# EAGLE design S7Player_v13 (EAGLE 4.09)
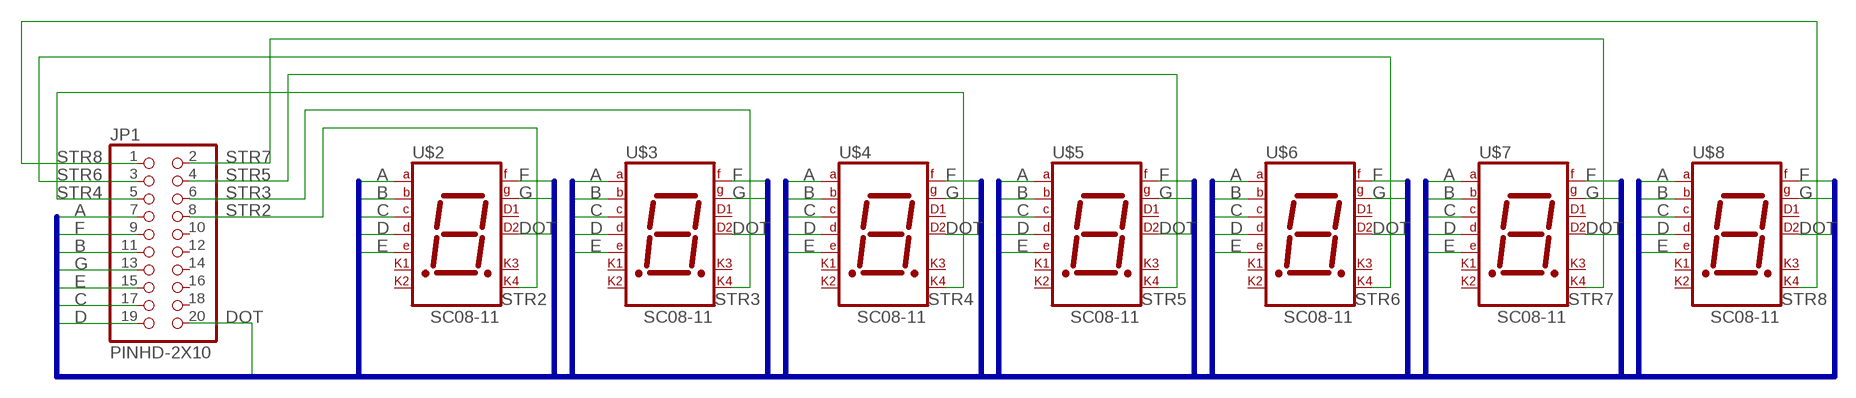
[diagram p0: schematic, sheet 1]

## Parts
JP1  PINHD-2X10  [2X10]
U$2  SC08-11  [SC08-11]
U$3  SC08-11  [SC08-11]
U$4  SC08-11  [SC08-11]
U$5  SC08-11  [SC08-11]
U$6  SC08-11  [SC08-11]
U$7  SC08-11  [SC08-11]
U$8  SC08-11  [SC08-11]

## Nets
A: JP1.7 U$2.1(A) U$3.1(A) U$4.1(A) U$5.1(A) U$6.1(A) U$7.1(A) U$8.1(A)
B: JP1.11 U$2.14(B) U$3.14(B) U$4.14(B) U$5.14(B) U$6.14(B) U$7.14(B) U$8.14(B)
C: JP1.17 U$2.12(C) U$3.12(C) U$4.12(C) U$5.12(C) U$6.12(C) U$7.12(C) U$8.12(C)
D: JP1.19 U$2.10(D) U$3.10(D) U$4.10(D) U$5.10(D) U$6.10(D) U$7.10(D) U$8.10(D)
DOT: JP1.20 U$2.9(D2) U$3.9(D2) U$4.9(D2) U$5.9(D2) U$6.9(D2) U$7.9(D2) U$8.9(D2)
E: JP1.15 U$2.4(E) U$3.4(E) U$4.4(E) U$5.4(E) U$6.4(E) U$7.4(E) U$8.4(E)
F: JP1.9 U$2.2(F) U$3.2(F) U$4.2(F) U$5.2(F) U$6.2(F) U$7.2(F) U$8.2(F)
G: JP1.13 U$2.13(G) U$3.13(G) U$4.13(G) U$5.13(G) U$6.13(G) U$7.13(G) U$8.13(G)
STR2: JP1.8 U$2.16(M4)
STR3: JP1.6 U$3.16(M4)
STR4: JP1.5 U$4.16(M4)
STR5: JP1.4 U$5.16(M4)
STR6: JP1.3 U$6.16(M4)
STR7: JP1.2 U$7.16(M4)
STR8: JP1.1 U$8.16(M4)
Unconnected: JP1.10 JP1.12 JP1.14 JP1.16 JP1.18 U$2.3(M1) U$2.5(M2) U$2.6(D1) U$2.11(M3) U$3.3(M1) U$3.5(M2) U$3.6(D1) U$3.11(M3) U$4.3(M1) U$4.5(M2) U$4.6(D1) U$4.11(M3) U$5.3(M1) U$5.5(M2) U$5.6(D1) U$5.11(M3) U$6.3(M1) U$6.5(M2) U$6.6(D1) U$6.11(M3) U$7.3(M1) U$7.5(M2) U$7.6(D1) U$7.11(M3) U$8.3(M1) U$8.5(M2) U$8.6(D1) U$8.11(M3)

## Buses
BUS:A,B,C,D,E,F,G,DOT

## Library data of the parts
JP1 = PINHEAD:PINHD-2X10
U$2-U$8 = SPECIAL:SC08-11

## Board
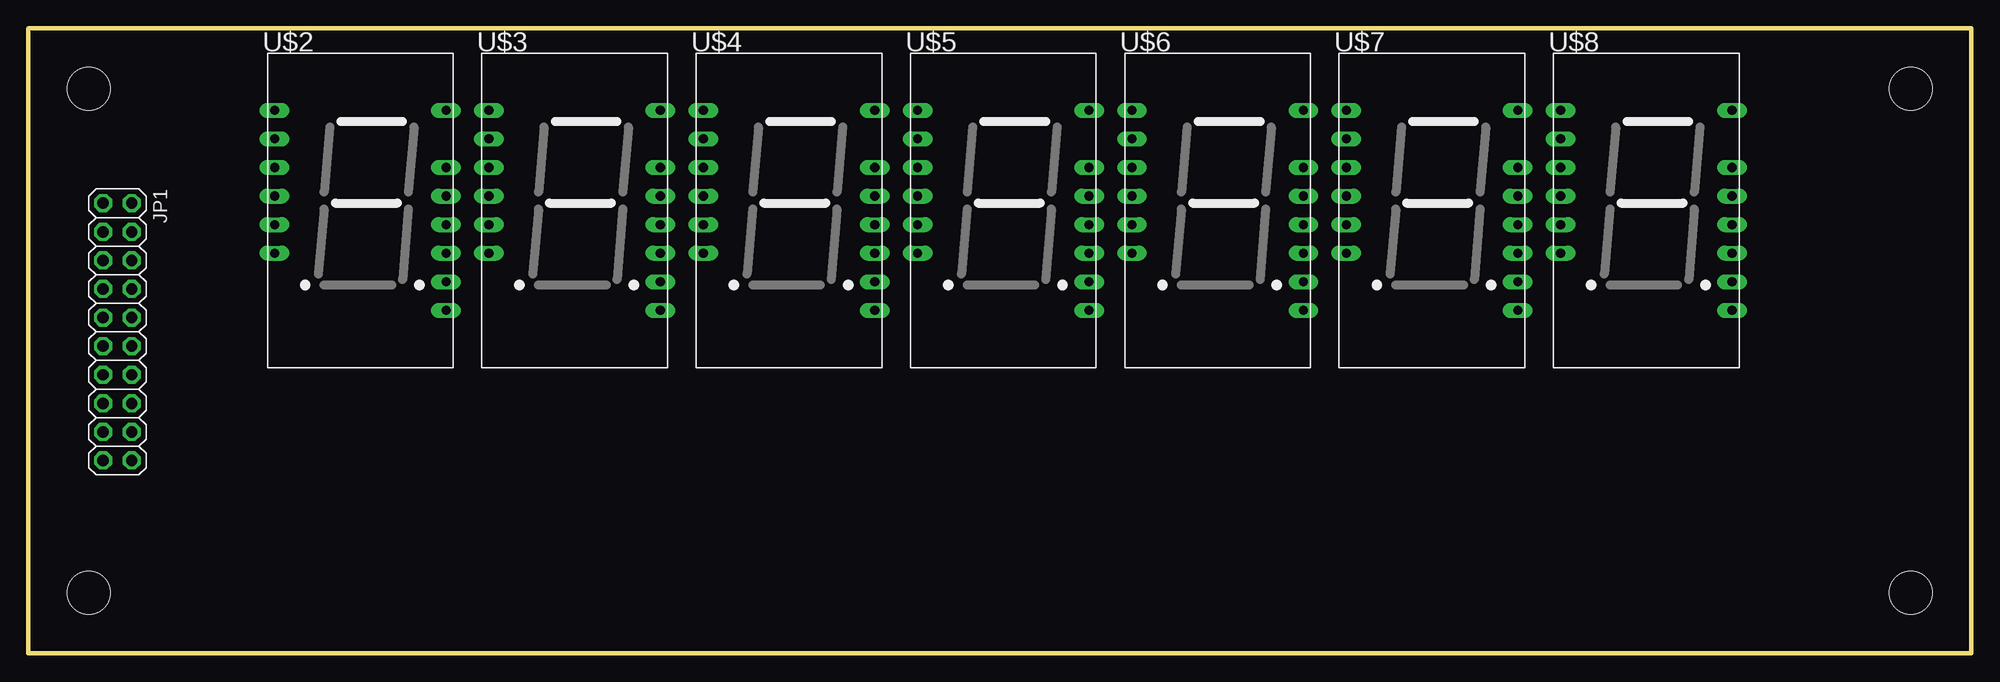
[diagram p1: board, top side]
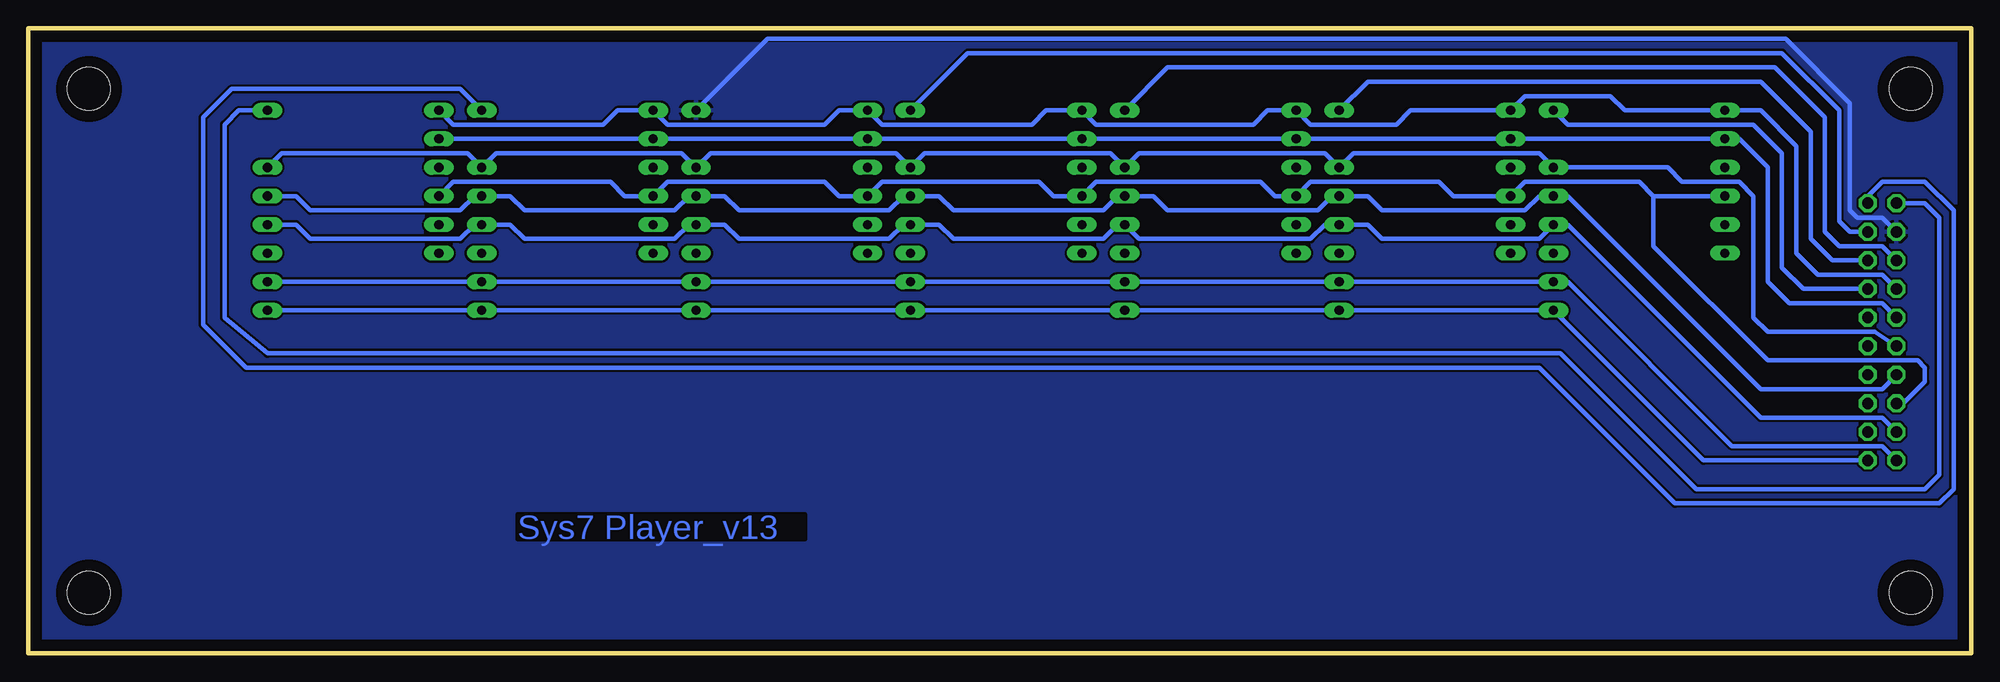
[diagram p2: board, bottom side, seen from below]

Size 172.72 x 55.56 mm. Coordinates in mm from the lower left corner, seen from the top.
Outline: 0,0 172.72,0 172.72,55.56 0,55.56 0,0
Copper layers used: Bottom
Holes 3.81 mm at 5.4,50.16 167.32,50.16 5.4,5.4 167.32,5.4
bKeepout: area 112.1,8.9 to 129.9,14

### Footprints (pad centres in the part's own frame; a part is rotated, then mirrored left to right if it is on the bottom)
2X10 = drill 1.016 pad 1.6 octagon: 1 -11.43,-1.27; 2 -11.43,1.27; 3 -8.89,-1.27; 4 -8.89,1.27; 5 -6.35,-1.27; 6 -6.35,1.27; 7 -3.81,-1.27; 8 -3.81,1.27; 9 -1.27,-1.27; 10 -1.27,1.27; 11 1.27,-1.27; 12 1.27,1.27; 13 3.81,-1.27; 14 3.81,1.27; 15 6.35,-1.27; 16 6.35,1.27; 17 8.89,-1.27; 18 8.89,1.27; 19 11.43,-1.27; 20 11.43,1.27
SC08-11 = drill 0.813 pad 1.27 long: 1 0,17.78; 2 0,15.24; 3 0,12.7; 4 0,10.16; 5 0,7.62; 6 0,5.08; 9 15.24,0; 10 15.24,2.54; 11 15.24,5.08; 12 15.24,7.62; 13 15.24,10.16; 14 15.24,12.7; 16 15.24,17.78

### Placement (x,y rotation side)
JP1  7.94,28.57 270 top
U$2  21.91,30.48 0 top
U$3  40.96,30.48 0 top
U$4  60.01,30.48 0 top
U$5  79.06,30.48 0 top
U$6  98.11,30.48 0 top
U$7  117.16,30.48 0 top
U$8  136.21,30.48 0 top

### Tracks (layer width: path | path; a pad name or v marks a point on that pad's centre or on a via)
A
  Bottom 0.406: U$8.1 134.94,46.99 121.6,46.99 120.33,48.26 U$7.1 115.89,46.99 101.92,46.99 100.65,48.26 U$6.1 96.84,46.99 83.5,46.99 82.23,48.26 U$5.1 77.79,46.99 63.82,46.99 62.55,48.26 U$4.1 58.74,46.99 51.12,46.99 49.85,48.26 U$3.1 39.69,49.53 32.07,49.53 30.8,48.26 U$2.1 18.73,48.26 15.56,45.09 15.56,35.56 13.65,33.65 7.94,33.65 JP1.7
B
  Bottom 0.406: U$8.14 150.18,44.45 133.67,44.45 U$7.14 131.13,44.45 114.62,44.45 U$6.14 112.08,44.45 95.57,44.45 U$5.14 93.03,44.45 76.52,44.45 U$4.14 73.98,44.45 57.47,44.45 U$3.14 54.93,44.45 38.42,44.45 U$2.14 26.99,43.18 25.72,41.91 20.64,41.91 19.37,40.64 19.37,29.84 18.1,28.57 8.57,28.57 JP1.11
C
  Bottom 0.406: U$8.12 148.91,38.1 147.64,36.83 134.3,36.83 133.03,38.1 U$7.12 129.86,38.1 128.59,36.83 115.25,36.83 113.98,38.1 U$6.12 110.81,38.1 109.54,36.83 96.2,36.83 94.93,38.1 U$5.12 91.76,38.1 90.49,36.83 77.15,36.83 75.88,38.1 U$4.12 73.98,36.83 58.74,36.83 57.47,38.1 U$3.12 53.66,38.1 52.39,36.83 38.42,36.83 U$2.12 35.88,38.1 18.73,20.95 7.94,20.95 JP1.17
D
  Bottom 0.406: U$8.10 U$7.10 U$6.10 U$5.10 U$4.10 U$3.10 U$2.10 35.88,33.02 21.27,18.41 7.94,18.41 JP1.19
DOT
  Bottom 0.406: JP1.20 23.81,17.15 U$2.9 U$3.9 | U$3.9 U$4.9 | U$4.9 U$5.9 U$6.9 | U$6.9 113.98,30.48 | U$6.9 U$7.9 U$8.9 | U$3.9 U$4.9
E
  Bottom 0.406: 28.26,40.64 U$2.4 | 28.26,40.64 29.53,41.91 39.69,41.91 U$3.4 46.04,40.64 47.31,41.91 58.74,41.91 U$4.4 61.91,40.64 63.18,41.91 77.79,41.91 U$5.4 81.6,40.64 82.87,41.91 96.84,41.91 U$6.4 100.65,40.64 101.92,41.91 115.89,41.91 U$7.4 119.7,40.64 120.97,41.91 134.94,41.91 U$8.4 | JP1.15 6.03,22.23 4.13,24.13 4.13,25.4 4.76,26.04 18.1,26.04 28.26,36.2 28.26,40.64
F
  Bottom 0.406: U$5.2 U$4.2 U$3.2 U$2.2 20.64,45.72 18.1,43.18 18.1,33.02 16.19,31.12 7.94,31.12 JP1.9 | U$5.2 U$6.2 | U$8.2 U$7.2 U$5.2
G
  Bottom 0.406: U$8.13 148.91,40.64 147.64,39.37 134.3,39.37 133.03,40.64 U$7.13 129.86,40.64 128.59,39.37 115.25,39.37 113.98,40.64 U$6.13 110.81,40.64 109.54,39.37 96.2,39.37 94.93,40.64 U$5.13 91.76,40.64 90.49,39.37 77.15,39.37 75.88,40.64 U$4.13 72.71,40.64 71.44,39.37 58.1,39.37 56.83,40.64 U$3.13 53.66,40.64 52.39,39.37 39.69,39.37 38.42,40.64 U$2.13 35.88,40.64 18.73,23.49 7.94,23.49 JP1.13
STR2
  Bottom 0.406: U$2.16 35.88,46.99 19.37,46.99 16.83,44.45 16.83,34.29 14.92,32.38 JP1.8
STR3
  Bottom 0.406: U$3.16 53.66,50.8 18.73,50.8 14.29,46.35 14.29,36.83 12.38,34.93 JP1.6
STR4
  Bottom 0.406: U$4.16 71.44,52.07 17.46,52.07 13.02,47.62 13.02,37.46 11.75,36.2 7.94,36.2 JP1.5
STR5
  Bottom 0.406: U$5.16 89.22,53.34 16.83,53.34 11.75,48.26 11.75,38.42 10.8,37.46 JP1.4
STR6
  Bottom 0.406: JP1.3 7.94,38.73 10.16,38.73 10.8,39.37 10.8,48.9 16.51,54.61 107,54.61 U$6.16
  pour Bottom: 0,55.56 0,0 172.72,0 172.72,55.56
STR7
  Bottom 0.406: U$7.16 134.3,50.16 154.62,50.16 157.16,47.62 157.16,29.21 153.35,25.4 38.42,25.4 26.35,13.34 2.86,13.34 1.59,14.6 1.59,39.37 4.13,41.91 7.94,41.91 9.21,40.64 JP1.2
STR8
  Bottom 0.406: U$8.16 153.99,48.26 155.26,46.99 155.26,29.84 151.45,26.67 36.51,26.67 24.45,14.6 4.13,14.6 2.86,15.88 2.86,38.73 4.13,40.01 JP1.1

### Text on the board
Bottom: Sys7 Player_v13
